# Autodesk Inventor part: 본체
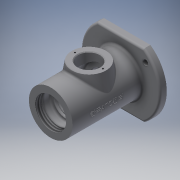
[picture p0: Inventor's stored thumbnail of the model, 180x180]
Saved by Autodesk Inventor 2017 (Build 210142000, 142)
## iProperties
Part Number: 본체
Material: 일반
Document SubType Name: Modeling
Designer: MRC
Density: 1 g/cm^3
Appearance: 기본값
Author: MRC
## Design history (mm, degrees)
sketch "스케치1"
  geometry: C1 r 32 at (0, 0); 1 further point
  constraints: 1 centre point, 1 coincident
  dimensions: "d0" = 64 diameter of C1
extrude "돌출1" new body sketch "스케치1" distance "d1" = 102; taper "d2" = 0 deg
sketch "스케치2"
  geometry: L1 (-58, 0)-(58, 0); L2 (-33.985, 47)-(33.985, 47); L3 (-33.985, -47)-(33.985, -47); A1 r 58 centre (0, 0) between (-33.985, 47) and (-33.985, -47); A2 r 58 centre (0, 0) between (33.985, -47) and (33.985, 47); 1 further point
  constraints: 6 end point, 6 point on circle, 2 centre point, 2 parallel, 1 coincident, 1 horizontal
  dimensions: "d4" = 47 distance between parallel lines of L1 L2; "d5" = 47 distance between parallel lines of L1 L3; "d6" = 58 radius of A1; "d7" = 58 radius of A2; "d8" = 67.97058 distance of L3.start L3.end
extrude "돌출2" join sketch "스케치2" distance "d9" = 10; taper "d10" = 0 deg
sketch "스케치3"
  geometry: C1 r 36 at (0, 0); 1 further point
  constraints: 1 centre point, 1 coincident
  dimensions: "d11" = 72 diameter of C1
extrude "돌출3" join sketch "스케치3" distance "d12" = 3; taper "d13" = 0 deg
sketch "스케치6"
  geometry: L1 (-36.77, -30.854)-(76.739, 64.392); L2 (0, 0)-(48, 0); C1 r 4 at (36.77, 30.854); C2 r 4 at (-36.77, -30.854); A1 r 48 centre (0, 0) between (48, 0) and (36.77, 30.854); 1 further point
  constraints: 4 end point, 3 centre point, 3 point on circle, 2 coincident, 2 point on line, 1 horizontal
  dimensions: "d27" = 96 diameter of A1; "d28" = 40 deg angle of L2 L1; "d29" = 8 diameter of C1; "d30" = 8 diameter of C2
extrude "돌출6" cut sketch "스케치6" stored distance "d31" = 4.4; taper "d32" = 0 deg
sketch "스케치10"
  geometry: C1 r 22.5 at (0, 0); 1 further point
  constraints: 1 centre point, 1 coincident
  dimensions: "d89" = 45 diameter of C1
extrude "돌출7" cut sketch "스케치10" distance "d90" = 8; taper "d91" = 0 deg
sketch "스케치11"
  geometry: C1 r 24 at (0, 0); 1 further point
  constraints: 1 centre point, 1 coincident
  dimensions: "d92" = 48 diameter of C1
extrude "돌출8" cut sketch "스케치11" distance "d93" = 3; taper "d94" = 0 deg
sketch "스케치12"
  geometry: C1 r 22.5 at (0, 0); 1 further point
  constraints: 1 centre point, 1 coincident
  dimensions: "d95" = 45 diameter of C1
extrude "돌출9" cut sketch "스케치12" distance "d96" = 11; taper "d97" = 0 deg
sketch "스케치13"
  geometry: C1 r 17.5 at (0, 0); 1 further point
  constraints: 1 centre point, 1 coincident
  dimensions: "d98" = 35 diameter of C1
extrude "돌출10" cut sketch "스케치13" distance "d99" = 2.25; taper "d100" = 0 deg
sketch "스케치14"
  geometry: C1 r 18.5 at (0, 0); 1 further point
  constraints: 1 centre point, 1 coincident
  dimensions: "d101" = 37 diameter of C1
extrude "돌출11" cut sketch "스케치14" distance "d102" = 1.75; taper "d103" = 0 deg
sketch "스케치15"
  geometry: C1 r 17.5 at (0, 0); 1 further point
  constraints: 1 centre point, 1 coincident
  dimensions: "d104" = 35 diameter of C1
extrude "돌출12" cut sketch "스케치15" distance "d105" = 11; taper "d106" = 0 deg
sketch "스케치16"
  geometry: C1 r 27 at (0, 0); 1 further point
  constraints: 1 centre point, 1 coincident
  dimensions: "d107" = 54 diameter of C1
extrude "돌출13" cut sketch "스케치16" distance "d108" = 38; taper "d109" = 0 deg
sketch "스케치17"
  geometry: C1 r 17.5 at (0, 0); 1 further point
  constraints: 1 centre point, 1 coincident
  dimensions: "d110" = 35 diameter of C1
extrude "돌출14" cut sketch "스케치17" distance "d111" = 11; taper "d112" = 0 deg
sketch "스케치18"
  geometry: C1 r 15 at (0, 0); 1 further point
  constraints: 1 centre point, 1 coincident
  dimensions: "d113" = 30 diameter of C1
extrude "돌출15" cut sketch "스케치18" distance "d114" = 5; taper "d115" = 0 deg
sketch "스케치19"
  geometry: L1 (-36, -13)-(36, -13) reference; L2 (0, -13)-(0, 1); L3 (0, 1)-(-20, 1); L4 (-32, 0)-(32, 0) reference; L5 (-20, 1)-(-30, -13); L6 (-30, -13)-(0, -13); 1 further point
  constraints: 8 end point, 1 collinear, 1 midpoint, 1 parallel, 1 point on line, 1 vertical
  dimensions: "d116" = 14 distance of L2.start L2.end; "d118" = 20 distance of L2.end L3.end; "d119" = 30 distance of L2.start L5.end
revolve "회전1" sketch "스케치19" stored, may be unused: angle "d120" = 90 deg
sketch "스케치20"
  geometry: C1 r 11 at (0, 0); 1 further point
  constraints: 1 centre point, 1 coincident
  dimensions: "d121" = 22 diameter of C1
extrude "돌출16" cut sketch "스케치20" distance "d122" = 2; taper "d123" = 0 deg
sketch "스케치21"
  geometry: C1 r 15 at (0, 0); 1 further point
  constraints: 1 centre point, 1 coincident
  dimensions: "d124" = 30 diameter of C1
extrude "돌출17" cut sketch "스케치21" distance "d125" = 8; taper "d126" = 0 deg
feature "스레드1" dims "d127" = 10, "d128" = 0
node "작업 평면1"
sketch "스케치22"
  geometry: L1 (32, 102)-(-32, 102) reference; L2 (-33.985, 0)-(33.985, 0) reference; C1 r 25 at (0, 46); 2 further points
  constraints: 1 centre point, 1 midpoint, 1 vertical alignment
  dimensions: "d130" = 50 diameter of C1; "d131" = 56 distance from line of L1 C1.centre
extrude "돌출18" join sketch "스케치22" stored distance "d132" = 8; taper "d133" = 10 deg
sketch "스케치23"
  geometry: C1 r 16 at (0, 0); 1 further point
  constraints: 1 centre point
  dimensions: "d134" = 32 diameter of C1
extrude "돌출19" cut sketch "스케치23" distance "d135" = 41; taper "d136" = 0 deg
sketch "스케치24" dims "d138" = 41
  geometry: L1 (33.985, 46)-(-33.985, 46) reference; C1 r 25 at (0, 0) reference; 4 further points
  constraints: 2 horizontal alignment, 1 coincident, 1 midpoint, 2 other
hole "구멍1" sketch "스케치24" at (-20.5, 0) diameter "d139" = 2.459; stored, may be unused: countersink angle "d143" = 90 deg, drill point angle "d145" = 118 deg; dims "d140" = 6, "d141" = 4, "d142" = 2, "d144" = 8
fillet "모깎기1" dims "d146" = 0.5, "d147" = 3, "d148" = 0.6
fillet "모깎기2" dims "d149" = 3
fillet "모깎기3" dims "d150" = 3
fillet "모깎기4" dims "d151" = 3
chamfer "모따기1" distance "d152" = 1; stored, may be unused: second distance "d153" = 2, angle "d154" = 45 deg
chamfer "모따기2" distance "d155" = 1; stored, may be unused: second distance "d156" = 2, angle "d157" = 45 deg
chamfer "모따기3" distance "d158" = 1; stored, may be unused: second distance "d159" = 2, angle "d160" = 45 deg
chamfer "모따기4" distance "d161" = 1; stored, may be unused: second distance "d162" = 2, angle "d163" = 45 deg
fillet "모깎기5" dims "d164" = 3
fillet "모깎기6" dims "d165" = 3
fillet "모깎기7" dims "d166" = 3
chamfer "모따기5" distance "d167" = 1; stored, may be unused: second distance "d168" = 2, angle "d169" = 45 deg
node "작업 평면2"
sketch "스케치25"
  geometry: L1 (-47, -10)-(47, -10) reference; 2 further points
  constraints: 1 vertical alignment, 1 other
  dimensions: "d171" = 62 distance from line of L1 point (0, 52)
feature "엠보싱1" sketch "스케치25" dims "d172" = 0.5, "d173" = 0
chamfer "모따기6" distance "d174" = 0.7; stored, may be unused: second distance "d175" = 2, angle "d176" = 30 deg
node "솔리드1"
mirror "미러1"
other parameters: "d3" = 116, "d34" = 4, "d35" = 4, "d36" = 4, "d129" = 38, "d170" = 85.25
